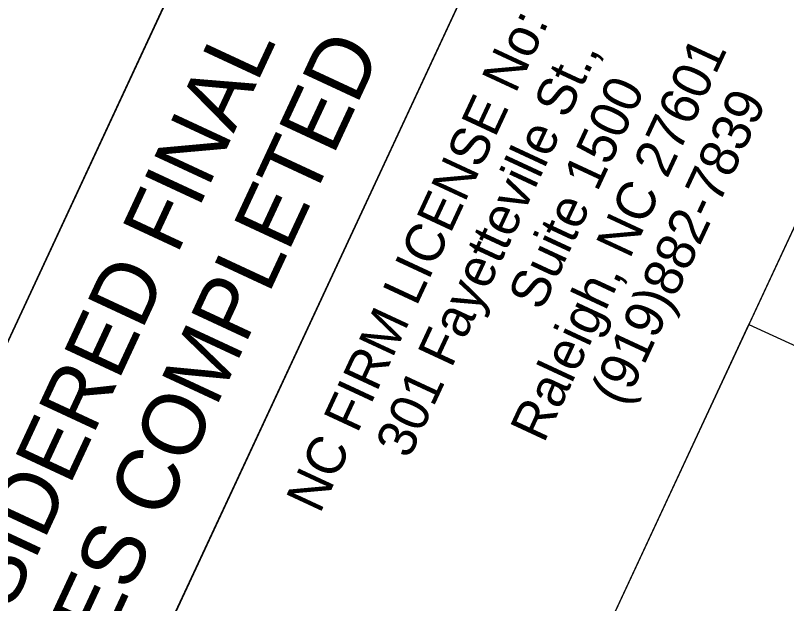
# Model space of a CAD drawing. Extents: x 2532214 to 2534758, y 714172 to 717266.
# Drawn here: x 2533040.9 to 2533109, y 716436.7 to 716488.6 of the extents above; entities that cross this region are included whole.
import ezdxf

# ---------------------------------------------------------------- set-up
doc = ezdxf.new("R2010")
doc.units = 0
for name, color, linetype in [('Dimension Lines CELL', 7, 'Continuous'), ('Mis Center Lines', 7, 'Continuous'), ('Structural Steel Angle 3 x 3', 7, 'Continuous'), ('Structural Steel Angle 3 x 3 Hidden', 7, 'Continuous'), ('Structural Steel Lines', 7, 'Continuous'), ('Text', 7, 'Continuous')]:
    doc.layers.add(name, color=color, linetype=linetype)

msp = doc.modelspace()

# ---------------------------------------------------------------- linework, layer by layer
at = {"layer": 'Dimension Lines CELL'}
msp.add_lwpolyline([(2533392.425, 716327.914), (2533206.821, 715928.977), (2532801.867, 715058.567), (2532325.862, 715280.027), (2532853.125, 716413.327), (2533042.373, 716325.28), (2533105.668, 716461.327), (2533324.425, 716359.551)], close=True, dxfattribs=at)
at = {"layer": 'Mis Center Lines'}
for p, q in [((2532989.172, 716350.031), (2533073.553, 716531.401)), ((2533094.86, 716521.488), (2533010.479, 716340.118))]:
    msp.add_line(p, q, dxfattribs=at)
at = {"layer": 'Structural Steel Angle 3 x 3'}
msp.add_lwpolyline([(2532325.862, 715280.027), (2532853.125, 716413.327), (2533042.373, 716325.28), (2533126.76, 716506.66), (2533345.516, 716404.885), (2533138.821, 715960.614), (2533229.488, 715918.431), (2532824.534, 715048.022)], close=True, dxfattribs=at)
at = {"layer": 'Structural Steel Angle 3 x 3 Hidden'}
msp.add_lwpolyline([(2533094.86, 716521.488), (2533010.479, 716340.118), (2533042.373, 716325.28), (2533126.755, 716506.649)], close=True, dxfattribs=at)
at = {"layer": 'Structural Steel Lines'}
msp.add_lwpolyline([(2532929.375, 716488.2), (2532971.557, 716578.868), (2533073.559, 716531.412), (2533031.376, 716440.744)], close=True, dxfattribs=at)

# ---------------------------------------------------------------- texts
at = {"layer": 'Mis Center Lines'}
for s, p in [('UNLESS ALL SIGNATURES COMPLETED', (2533013.28, 716356.462)), ('DOCUMENT NOT CONSIDERED FINAL', (2533007.44, 716364.772))]:
    msp.add_text(s, height=5.5, rotation=65.05, dxfattribs=at).set_placement(p)
at = {"layer": 'Text'}
for s, p in [('NC FIRM LICENSE No: C-1506', (2533067.795, 716444.521)), ('Raleigh, NC 27601', (2533087.567, 716450.748)), ('301 Fayetteville St., ', (2533075.67, 716449.357)), ('Suite 1500', (2533087.369, 716462.411)), ('(919)882-7839', (2533094.688, 716453.964))]:
    msp.add_text(s, height=3.4, rotation=65.05, dxfattribs=at).set_placement(p)

doc.saveas('drawing.dxf')
